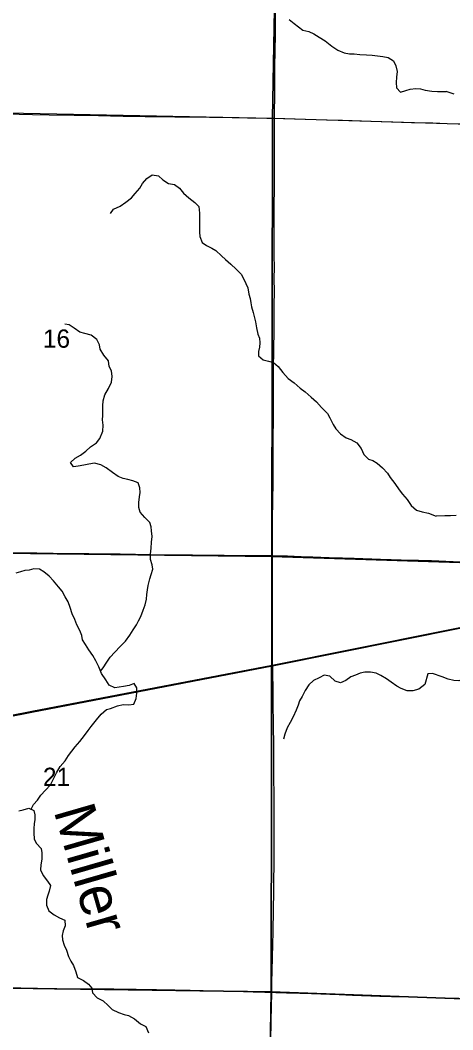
# Model space of a CAD drawing. Extents: x 0 to 34, y 0 to 22.
# Drawn here: x 3.097 to 4.092, y 18.428 to 20.749 of the extents above; entities that cross this region are included whole.
import ezdxf

# ---------------------------------------------------------------- set-up
doc = ezdxf.new("R2010")
doc.units = 0
for name, color, linetype in [('GM_X_County_Road', 7, 'Continuous'), ('GM_X_Minor_River', 7, 'Continuous'), ('GM_X_Minor_River_Text', 7, 'Continuous'), ('GM_X_Rail_Line', 7, 'Continuous'), ('GM_X_Rail_Line_Text', 7, 'Continuous'), ('GM_X_Section', 7, 'Continuous'), ('GM_X_Section_Text', 7, 'Continuous'), ('GM_X_Township_Road', 7, 'Continuous')]:
    doc.layers.add(name, color=color, linetype=linetype)

msp = doc.modelspace()

# ---------------------------------------------------------------- linework, layer by layer
at = {"layer": 'GM_X_County_Road'}
for points in [[(3.6824, 20.5235), (3.6824, 20.5408), (3.6827, 20.5712), (3.683, 20.6147), (3.6832, 20.6396), (3.684, 20.6806), (3.6843, 20.7129), (3.6846, 20.7689), (3.6857, 20.8249), (3.6863, 20.8634), (3.6868, 20.9)], [(3.6774, 19.518), (3.6774, 19.5444), (3.6776, 19.568), (3.6779, 19.6084), (3.6784, 19.6364), (3.6786, 19.6562), (3.6787, 19.6749), (3.6788, 19.7066), (3.6791, 19.7793), (3.6795, 19.839), (3.6797, 19.8825), (3.6801, 19.9266), (3.6802, 19.9565), (3.6804, 19.9813), (3.6812, 20.046), (3.6814, 20.069), (3.6817, 20.0951), (3.6818, 20.1237), (3.6816, 20.1566), (3.6818, 20.1784), (3.6815, 20.2094), (3.6815, 20.2368), (3.6815, 20.261), (3.6816, 20.2859), (3.6817, 20.3195), (3.6819, 20.3648), (3.6819, 20.3853), (3.682, 20.4351), (3.6823, 20.4892), (3.6823, 20.5109), (3.6824, 20.5235)], [(2.6937, 19.5326), (2.7132, 19.5319), (2.7468, 19.531), (2.8027, 19.53), (2.8935, 19.5284), (2.9233, 19.5281), (2.96, 19.5271), (2.9954, 19.5263), (3.0215, 19.5258), (3.0638, 19.5252), (3.0986, 19.5245), (3.1352, 19.5241), (3.1726, 19.5237), (3.2161, 19.5232), (3.2546, 19.5227), (3.3025, 19.5221), (3.3267, 19.5218), (3.3621, 19.5213), (3.3957, 19.5208), (3.4933, 19.5196), (3.5231, 19.5192), (3.566, 19.519), (3.6189, 19.5187), (3.6774, 19.518)], [(3.6758, 18.5145), (3.6762, 18.5386), (3.6767, 18.5629), (3.6774, 18.5958), (3.678, 18.6232), (3.6787, 18.6542), (3.6795, 18.704), (3.6803, 18.7462), (3.6811, 18.8326), (3.6812, 18.9016), (3.681, 18.9675), (3.6807, 19.0092), (3.6806, 19.0471), (3.6804, 19.09), (3.6802, 19.1198), (3.6798, 19.1391), (3.6794, 19.1696), (3.6791, 19.2081), (3.6785, 19.2509), (3.6777, 19.2845), (3.6777, 19.3255), (3.6778, 19.3516), (3.6773, 19.4182), (3.6772, 19.4654), (3.6774, 19.5095), (3.6774, 19.518)], [(3.6774, 19.518), (3.7121, 19.5174), (3.7432, 19.5163), (3.7706, 19.5153), (3.8078, 19.514), (3.8389, 19.513), (3.8656, 19.5119), (3.9264, 19.51), (3.9504, 19.5095), (3.9734, 19.5086), (4.0138, 19.5074), (4.0436, 19.5065), (4.0933, 19.5047), (4.1188, 19.5038), (4.1635, 19.5023), (4.1861, 19.5015)], [(3.0773, 18.525), (3.0983, 18.5244), (3.113, 18.5241), (3.1367, 18.5236), (3.1603, 18.523), (3.176, 18.5227), (3.1903, 18.5226), (3.2058, 18.5226), (3.2219, 18.5225), (3.2407, 18.5224), (3.2524, 18.5222), (3.2611, 18.5222), (3.2841, 18.522), (3.3127, 18.522), (3.3238, 18.5219), (3.3356, 18.5217), (3.3636, 18.5213), (3.3723, 18.5212), (3.3953, 18.5208), (3.4108, 18.5206), (3.4313, 18.5203), (3.4531, 18.5198), (3.4879, 18.5192), (3.5028, 18.5189), (3.5183, 18.5184), (3.5394, 18.5179), (3.5749, 18.5172), (3.611, 18.5163), (3.6327, 18.5158), (3.6597, 18.515), (3.6758, 18.5145)], [(3.6741, 18.4261), (3.6746, 18.4498), (3.6751, 18.4802), (3.6758, 18.5145)], [(3.6758, 18.5145), (3.6855, 18.5141), (3.7097, 18.5134), (3.7408, 18.5124), (3.7674, 18.5115), (3.8309, 18.5091), (3.8464, 18.5084), (3.8619, 18.5077), (3.8824, 18.507), (3.9247, 18.5056), (3.9514, 18.5048), (3.9999, 18.5036), (4.0223, 18.503), (4.0468, 18.5023), (4.0751, 18.5015), (4.1061, 18.5007)]]:
    msp.add_lwpolyline(points, dxfattribs=at)
at = {"layer": 'GM_X_Minor_River'}
for points in [[(3.7158, 20.7505), (3.7273, 20.7407), (3.7373, 20.7332), (3.7474, 20.7261), (3.7614, 20.7227), (3.7726, 20.7171), (3.7846, 20.7096), (3.7984, 20.7009), (3.814, 20.6891), (3.8275, 20.68), (3.8425, 20.6735), (3.8546, 20.6717), (3.8656, 20.671), (3.8784, 20.67), (3.8936, 20.6688), (3.9065, 20.6685), (3.9193, 20.667), (3.9311, 20.6652), (3.9435, 20.6626), (3.9562, 20.655), (3.9616, 20.6435), (3.9644, 20.6309), (3.9629, 20.618), (3.9622, 20.6051), (3.9626, 20.5933), (3.9719, 20.5832), (3.9841, 20.5871), (3.9944, 20.5899), (4.0074, 20.5918), (4.0184, 20.5911), (4.0285, 20.5875), (4.044, 20.5852), (4.0573, 20.5848), (4.0775, 20.5848)], [(4.0952, 20.5785), (4.0775, 20.5848)], [(3.3044, 20.3046), (3.3119, 20.3147), (3.3268, 20.3215), (3.34, 20.3303), (3.3531, 20.3406), (3.3617, 20.3506), (3.3719, 20.3629), (3.3786, 20.3733), (3.3884, 20.3852), (3.4008, 20.3933), (3.4151, 20.391), (3.4255, 20.3816), (3.4379, 20.3737), (3.4518, 20.3711), (3.4634, 20.3628), (3.473, 20.3515), (3.4852, 20.3402), (3.499, 20.33), (3.5078, 20.3203), (3.5094, 20.3054), (3.5095, 20.2955), (3.5092, 20.283), (3.5094, 20.2617), (3.5103, 20.2518), (3.5156, 20.238), (3.5253, 20.231), (3.5377, 20.2246), (3.5474, 20.2194), (3.56, 20.2069), (3.5697, 20.199), (3.5819, 20.1877), (3.5941, 20.1768), (3.6056, 20.1651), (3.611, 20.1547), (3.6164, 20.1432), (3.6207, 20.1332), (3.6234, 20.1187), (3.6262, 20.1091), (3.6275, 20.0992), (3.6291, 20.0897), (3.633, 20.0767), (3.6364, 20.0648), (3.6385, 20.0552), (3.6408, 20.0415), (3.6438, 20.0274), (3.6474, 20.0178), (3.6483, 20.0075), (3.6476, 19.9973), (3.6455, 19.9875), (3.6456, 19.9776), (3.6564, 19.9682), (3.6684, 19.9652), (3.6801, 19.9619), (3.6909, 19.9529), (3.7012, 19.9386), (3.7137, 19.9253), (3.7271, 19.9151), (3.7409, 19.903), (3.7524, 19.8943), (3.7662, 19.8826), (3.7788, 19.8716), (3.7902, 19.8588), (3.8039, 19.8448), (3.8093, 19.8351), (3.8169, 19.8198), (3.8235, 19.8093), (3.8338, 19.798), (3.8469, 19.789), (3.8578, 19.7853), (3.8713, 19.7773), (3.8815, 19.7642), (3.888, 19.7507), (3.8988, 19.7398), (3.9086, 19.7369), (3.9187, 19.7309), (3.9305, 19.72), (3.942, 19.7075), (3.9485, 19.6979), (3.9592, 19.6835), (3.9691, 19.6692), (3.9768, 19.6592), (3.9871, 19.6471), (3.9966, 19.6332), (4.0092, 19.6223), (4.0221, 19.6185), (4.0365, 19.616), (4.0545, 19.6086)], [(3.282, 19.2524), (3.288, 19.26), (3.2967, 19.2731), (3.3038, 19.2843), (3.3148, 19.2965), (3.3272, 19.3091), (3.3393, 19.3217), (3.3495, 19.3351), (3.3567, 19.3478), (3.3649, 19.3586), (3.369, 19.3684), (3.3749, 19.3785), (3.3798, 19.3924), (3.3843, 19.4052), (3.3873, 19.4177), (3.3887, 19.4287), (3.3902, 19.4396), (3.3915, 19.4495), (3.3954, 19.4649), (3.3983, 19.4747), (3.402, 19.4872), (3.4007, 19.4967), (3.3969, 19.5093), (3.3972, 19.5215), (3.3983, 19.5351), (3.3994, 19.5491), (3.4005, 19.562), (3.3993, 19.575), (3.3984, 19.5845), (3.3949, 19.5944), (3.3837, 19.6054), (3.3731, 19.6182), (3.3703, 19.6289), (3.3698, 19.6399), (3.3717, 19.6535), (3.3731, 19.6634), (3.3722, 19.6736), (3.3683, 19.6855), (3.3559, 19.69), (3.345, 19.6929), (3.3337, 19.6951), (3.3224, 19.7), (3.3094, 19.7094), (3.2948, 19.7201), (3.2829, 19.7268), (3.2678, 19.7303), (3.2548, 19.7283), (3.2434, 19.7263), (3.23, 19.7233), (3.2197, 19.722), (3.2131, 19.7317), (3.2233, 19.7424), (3.236, 19.7489), (3.2484, 19.7581), (3.2585, 19.7681), (3.2724, 19.7772), (3.2802, 19.7873), (3.2871, 19.8042), (3.2878, 19.8178), (3.2866, 19.83), (3.2873, 19.8403), (3.2872, 19.8528), (3.2874, 19.8623), (3.2881, 19.8737), (3.2919, 19.8876), (3.3002, 19.9018), (3.3071, 19.9168), (3.3085, 19.9297), (3.307, 19.943), (3.3015, 19.9527), (3.2999, 19.9656), (3.2897, 19.9788), (3.2813, 19.9923), (3.2792, 20.0022), (3.2735, 20.0149), (3.2601, 20.0248), (3.2458, 20.0285), (3.2341, 20.0319), (3.2214, 20.0409), (3.2098, 20.0488), (3.2, 20.0499)], [(4.0743, 19.6096), (4.0545, 19.6086)], [(4.1001, 19.6102), (4.0872, 19.6093), (4.0743, 19.6096)], [(3.1219, 18.9353), (3.1279, 18.9459), (3.1365, 18.9563), (3.1443, 18.9671), (3.1549, 18.9786), (3.1666, 18.9916), (3.1738, 19.0047), (3.1806, 19.0186), (3.1889, 19.0332), (3.2006, 19.0462), (3.2081, 19.0585), (3.216, 19.0686), (3.2231, 19.0786), (3.234, 19.0905), (3.245, 19.1043), (3.2533, 19.1158), (3.2603, 19.1255), (3.2729, 19.1404), (3.2831, 19.1538), (3.2955, 19.1641), (3.305, 19.1669), (3.3207, 19.1726), (3.3337, 19.1757), (3.3466, 19.1753), (3.3588, 19.1765), (3.3637, 19.1893), (3.3651, 19.2018), (3.3651, 19.214), (3.3596, 19.2243), (3.3481, 19.2193), (3.3344, 19.2174), (3.3245, 19.2158), (3.315, 19.2145), (3.3018, 19.2201), (3.2938, 19.2329), (3.2843, 19.2472), (3.2778, 19.2622), (3.271, 19.2764), (3.2645, 19.2883), (3.2546, 19.3015), (3.2473, 19.3134), (3.2407, 19.3242), (3.2387, 19.3342), (3.2341, 19.3457), (3.2276, 19.3591), (3.2226, 19.371), (3.2164, 19.3841), (3.2119, 19.3987), (3.2073, 19.4117), (3.2007, 19.4236), (3.1935, 19.4367), (3.1854, 19.4464), (3.174, 19.46), (3.1636, 19.4709), (3.1513, 19.4807), (3.1416, 19.4867), (3.128, 19.4874), (3.1173, 19.4846), (3.1078, 19.4838), (3.0975, 19.4806), (3.0871, 19.4774)], [(4.046, 19.2474), (4.0353, 19.2464), (4.0279, 19.2215), (4.0143, 19.2109), (4.0002, 19.2071), (3.9873, 19.207), (3.9738, 19.2123), (3.9633, 19.2179), (3.9506, 19.2273), (3.9398, 19.2348), (3.9271, 19.2424), (3.9158, 19.2476), (3.903, 19.2502), (3.8897, 19.2498), (3.8794, 19.2478), (3.8683, 19.2435), (3.8579, 19.2396), (3.8459, 19.2308), (3.834, 19.2254), (3.822, 19.2295), (3.8098, 19.2412), (3.7965, 19.2431), (3.785, 19.2373), (3.7716, 19.2308), (3.7614, 19.2208), (3.7528, 19.2081), (3.7456, 19.1939), (3.7396, 19.1842), (3.7363, 19.1744), (3.7323, 19.1627), (3.7254, 19.1477), (3.7182, 19.1342), (3.7111, 19.1219), (3.7058, 19.1079), (3.7028, 19.0959)], [(4.2019, 19.2447), (4.191, 19.2494), (4.1782, 19.255), (4.1664, 19.2529), (4.1515, 19.2475), (4.1408, 19.2432), (4.129, 19.24), (4.1175, 19.2338), (4.106, 19.2306), (4.0947, 19.2308), (4.0815, 19.2341), (4.0683, 19.2396), (4.046, 19.2474)], [(3.0941, 18.9312), (3.1036, 18.934), (3.117, 18.9375), (3.1286, 18.9322), (3.1307, 18.9223), (3.1304, 18.9113), (3.129, 18.9015), (3.1287, 18.8908), (3.1281, 18.8806), (3.1293, 18.8665), (3.1343, 18.8565), (3.145, 18.8449), (3.1467, 18.8349), (3.1467, 18.8201), (3.1448, 18.8077), (3.1434, 18.7959), (3.1499, 18.7828), (3.1602, 18.7697), (3.1664, 18.76), (3.1634, 18.7472), (3.1609, 18.7374), (3.1576, 18.7276), (3.1576, 18.7147), (3.163, 18.702), (3.1749, 18.6922), (3.1876, 18.6858)], [(3.1876, 18.6858), (3.1996, 18.6802), (3.2004, 18.6669), (3.196, 18.656), (3.1938, 18.645), (3.1947, 18.6351), (3.1982, 18.6229), (3.2032, 18.611), (3.2085, 18.5968), (3.2136, 18.5857), (3.2194, 18.5756), (3.2247, 18.5611), (3.2289, 18.5481), (3.2424, 18.5416), (3.254, 18.5334), (3.2617, 18.5237), (3.2637, 18.5134), (3.274, 18.5013), (3.2879, 18.4945), (3.2994, 18.4844), (3.3083, 18.4746), (3.3233, 18.4678), (3.3361, 18.4637), (3.3463, 18.4611), (3.3597, 18.4536), (3.3735, 18.4422), (3.3862, 18.4354), (3.3919, 18.4216)]]:
    msp.add_lwpolyline(points, dxfattribs=at)
at = {"layer": 'GM_X_Rail_Line'}
for points in [[(2.1, 18.9599), (2.5738, 19.0523), (3.1234, 19.1602), (3.6767, 19.2666), (4.2609, 19.3838), (4.9006, 19.5087), (5.4948, 19.6259), (6.096, 19.7423), (6.7148, 19.8649), (7.2736, 19.9767), (7.8416, 20.0877), (8.2886, 20.1741), (8.3633, 20.1886), (8.9, 20.2933)], [(2.1, 18.9575), (2.5743, 19.05), (3.1238, 19.158), (3.6772, 19.2644), (4.2614, 19.3816), (4.9011, 19.5065), (5.4953, 19.6236), (6.0964, 19.7401), (6.7153, 19.8626), (7.2741, 19.9744), (7.8421, 20.0855), (8.2891, 20.1718), (8.3637, 20.1864), (8.9, 20.2909)]]:
    msp.add_lwpolyline(points, dxfattribs=at)
at = {"layer": 'GM_X_Rail_Line_Text'}
for points in [[(3.6842, 20.9), (2.7013, 20.9), (2.684, 20.5432), (3.6779, 20.5235)], [(4.6953, 20.9), (3.6842, 20.9), (3.6779, 20.5235), (4.6829, 20.4926)]]:
    msp.add_lwpolyline(points, close=True, dxfattribs=at)
at = {"layer": 'GM_X_Section'}
for points in [[(2.684, 20.5432), (3.6779, 20.5235), (3.6762, 19.5163), (2.687, 19.5286)], [(3.6779, 20.5235), (4.6829, 20.4926), (4.6614, 19.4847), (3.6762, 19.5163)], [(2.687, 19.5286), (3.6762, 19.5163), (3.6746, 18.5151), (2.687, 18.5293), (2.687, 18.5441)], [(3.6762, 19.5163), (4.6614, 19.4847), (4.6642, 18.4797), (3.6746, 18.5151)], [(2.687, 18.5293), (3.6746, 18.5151), (3.6575, 17.498), (2.649, 17.5241), (2.6545, 17.8761)], [(3.6746, 18.5151), (4.6642, 18.4797), (4.6605, 17.4748), (3.6575, 17.498)]]:
    msp.add_lwpolyline(points, close=True, dxfattribs=at)
at = {"layer": 'GM_X_Township_Road'}
for points in [[(3.6824, 20.5235), (3.6824, 20.5408), (3.6827, 20.5712), (3.683, 20.6147), (3.6832, 20.6396), (3.684, 20.6806), (3.6843, 20.7129), (3.6846, 20.7689), (3.6857, 20.8249), (3.6863, 20.8634), (3.6868, 20.9)], [(2.6876, 20.5444), (2.6901, 20.5443), (2.7746, 20.5415), (2.8889, 20.5381), (2.9362, 20.5366), (3.0058, 20.5347), (3.0642, 20.5333), (3.1251, 20.5319), (3.1636, 20.531), (3.2208, 20.5302), (3.2774, 20.5296), (3.3047, 20.529), (3.334, 20.5283), (3.3607, 20.528), (3.3849, 20.5276), (3.4191, 20.5273), (3.4527, 20.5267), (3.4906, 20.5262), (3.5322, 20.5256), (3.5845, 20.5247), (3.6199, 20.5241), (3.6646, 20.5238), (3.6808, 20.5235), (3.6824, 20.5235)], [(3.6774, 19.518), (3.6774, 19.5444), (3.6776, 19.568), (3.6779, 19.6084), (3.6784, 19.6364), (3.6786, 19.6562), (3.6787, 19.6749), (3.6788, 19.7066), (3.6791, 19.7793), (3.6795, 19.839), (3.6797, 19.8825), (3.6801, 19.9266), (3.6802, 19.9565), (3.6804, 19.9813), (3.6812, 20.046), (3.6814, 20.069), (3.6817, 20.0951), (3.6818, 20.1237), (3.6816, 20.1566), (3.6818, 20.1784), (3.6815, 20.2094), (3.6815, 20.2368), (3.6815, 20.261), (3.6816, 20.2859), (3.6817, 20.3195), (3.6819, 20.3648), (3.6819, 20.3853), (3.682, 20.4351), (3.6823, 20.4892), (3.6823, 20.5109), (3.6824, 20.5235)], [(3.6824, 20.5235), (3.7299, 20.5221), (3.802, 20.5199), (3.8386, 20.5188), (3.9045, 20.5166), (3.997, 20.5139), (4.0461, 20.5126), (4.0797, 20.5114), (4.112, 20.5103), (4.1461, 20.5091), (4.1921, 20.508), (4.2462, 20.5063), (4.2841, 20.5046), (4.3064, 20.5036), (4.3294, 20.503), (4.3555, 20.5023), (4.404, 20.5011), (4.4506, 20.5001), (4.4792, 20.4995), (4.4922, 20.4989)], [(3.6758, 18.5145), (3.6762, 18.5386), (3.6767, 18.5629), (3.6774, 18.5958), (3.678, 18.6232), (3.6787, 18.6542), (3.6795, 18.704), (3.6803, 18.7462), (3.6811, 18.8326), (3.6812, 18.9016), (3.681, 18.9675), (3.6807, 19.0092), (3.6806, 19.0471), (3.6804, 19.09), (3.6802, 19.1198), (3.6798, 19.1391), (3.6794, 19.1696), (3.6791, 19.2081), (3.6785, 19.2509), (3.6777, 19.2845), (3.6777, 19.3255), (3.6778, 19.3516), (3.6773, 19.4182), (3.6772, 19.4654), (3.6774, 19.5095), (3.6774, 19.518)], [(3.6741, 18.4261), (3.6746, 18.4498), (3.6751, 18.4802), (3.6758, 18.5145)]]:
    msp.add_lwpolyline(points, dxfattribs=at)

# ---------------------------------------------------------------- texts
at = {"layer": 'GM_X_Minor_River_Text'}
msp.add_text('Miller', height=0.09476, rotation=286.0959, dxfattribs=at).set_placement((3.1736, 18.9316))
at = {"layer": 'GM_X_Section_Text'}
for s, p in [('16', (3.1494, 19.9959)), ('21', (3.1494, 18.9887))]:
    msp.add_text(s, height=0.04186, rotation=0, dxfattribs=at).set_placement(p)

doc.saveas('drawing.dxf')
